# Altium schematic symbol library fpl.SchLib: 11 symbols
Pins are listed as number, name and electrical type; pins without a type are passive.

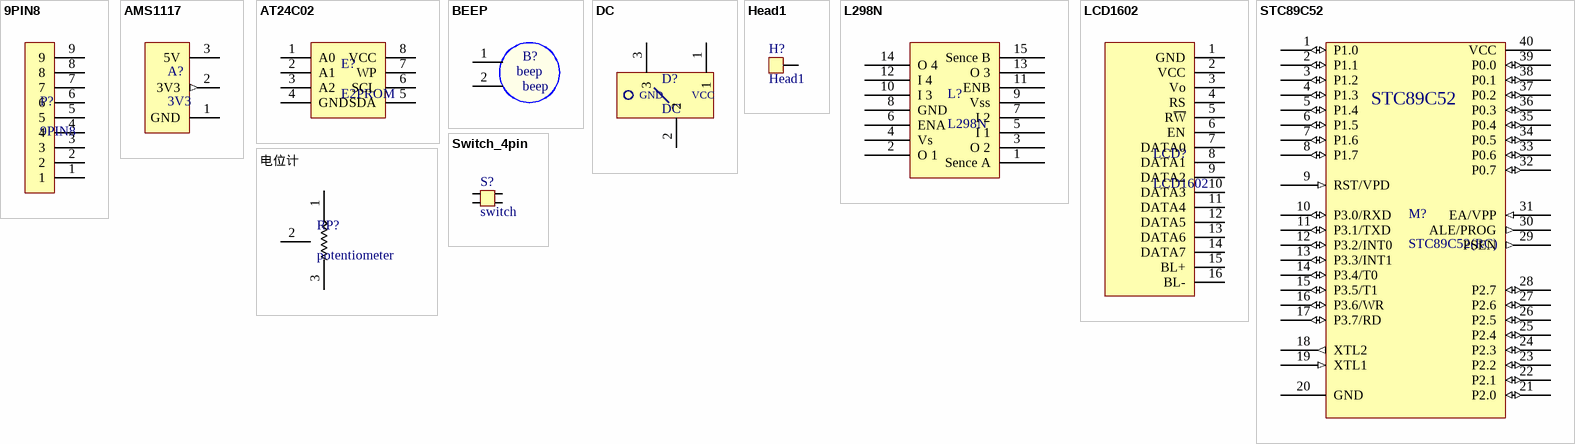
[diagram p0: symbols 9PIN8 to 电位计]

## 9PIN8
designator P?
9PIN8排阻
pins: 1, 2, 3, 4, 5, 6, 7, 8, 9

## AMS1117
designator A?, comment 3V3
3.3V电源模块, 5V to 3.3V
pins: 1 GND, 2 3V3 (out), 3 5V (power)

## AT24C02
designator E?, comment E2PROM
E2PROM,I2C-上拉
pins: 1 A0, 2 A1, 3 A2, 4 GND, 5 SDA, 6 SCL, 7 WP, 8 VCC

## BEEP
designator B?, comment beep
蜂鸣器
pins: 1, 2

## DC
designator D?
DC插座
pins: 1, 2, 3

## Head1
designator H?
1pin焊盘
pins: 1 H?

## L298N
designator L?
电机驱动芯片
pins: 1 Sence A, 2 O 1, 3 O 2, 4 Vs, 5 I 1, 6 ENA, 7 I 2, 8 GND, 9 Vss, 10 I 3, 11 ENB, 12 I 4, 13 O 3, 14 O 4, 15 Sence B

## LCD1602
designator LCD?
pins: 1 GND, 2 VCC, 3 Vo, 4 RS, 5 R~{W}, 6 EN, 7 DATA0, 8 DATA1, 9 DATA2, 10 DATA3, 11 DATA4, 12 DATA5, 13 DATA6, 14 DATA7, 15 BL+, 16 BL-

## STC89C52
designator M?, comment STC89C52(RC)
MCU
pins: 1 P1.0 (io), 2 P1.1 (io), 3 P1.2 (io), 4 P1.3 (io), 5 P1.4 (io), 6 P1.5 (io), 7 P1.6 (io), 8 P1.7 (io), 9 RST/VPD (in), 10 P3.0/RXD (io), 11 P3.1/TXD (io), 12 P3.2/INT0 (io), 13 P3.3/INT1 (io), 14 P3.4/T0 (io), 15 P3.5/T1 (io), 16 P3.6/WR (io), 17 P3.7/RD (io), 18 XTL2 (out), 19 XTL1 (in), 20 GND, 21 P2.0 (io), 22 P2.1 (io), 23 P2.2 (io), 24 P2.3 (io), 25 P2.4 (io), 26 P2.5 (io), 27 P2.6 (io), 28 P2.7 (io), 29 PSEN (out), 30 ALE/PROG (out), 31 EA/VPP (in), 32 P0.7 (io), 33 P0.6 (io), 34 P0.5 (io), 35 P0.4 (io), 36 P0.3 (io), 37 P0.2 (io), 38 P0.1 (io), 39 P0.0 (io), 40 VCC

## Switch_4pin
designator S?, comment switch
单稳态按钮开关
pins: 0, 1, 2, 3

## 电位计
designator RP?, comment potentiometer
旋钮式电位计
pins: 1, 2, 3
